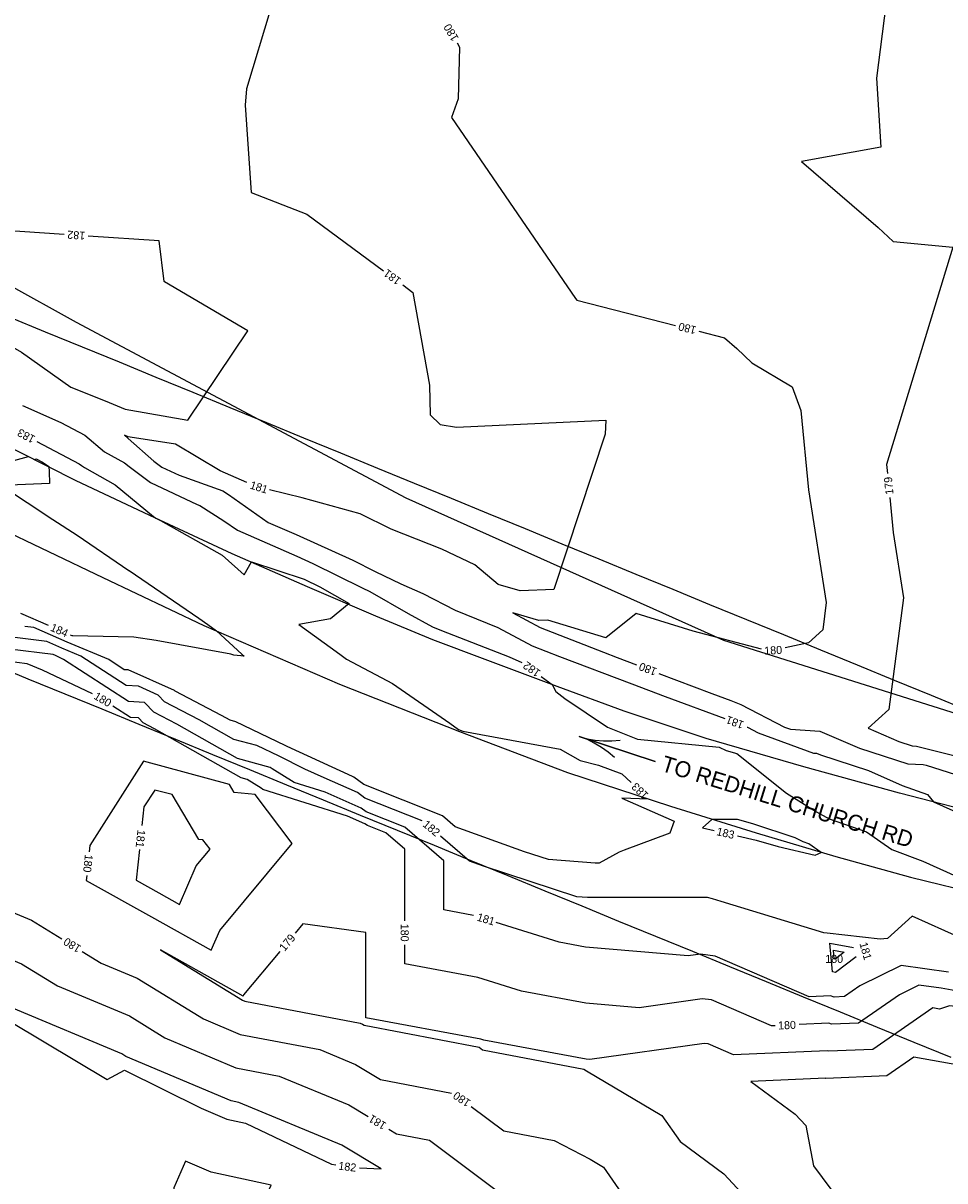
# Model space of a CAD drawing. Extents: x 2086416 to 2115205, y 575507 to 632762.
# Drawn here: x 2110689 to 2110919.3, y 581570.2 to 581859.5 of the extents above; entities that cross this region are included whole.
import ezdxf

# ---------------------------------------------------------------- set-up
doc = ezdxf.new("R2010")
doc.units = 0
for name, color, linetype in [('DTM Contours Major', 7, 'Continuous'), ('DTM Contours Major Text', 7, 'Continuous'), ('DTM Contours Minor', 7, 'Continuous'), ('DTM Contours Minor Text', 7, 'Continuous'), ('Exist Hydrographic FEMA Cross Section', 7, 'Continuous'), ('Exist Roads EOP', 7, 'Continuous'), ('Exist Roads EOP Text', 7, 'Continuous'), ('Exist Vegetation Woods Line', 7, 'Continuous')]:
    doc.layers.add(name, color=color, linetype=linetype)

msp = doc.modelspace()

# ---------------------------------------------------------------- linework, layer by layer
at = {"layer": 'DTM Contours Major'}
for points in [[(2110797.42, 581854.62), (2110798.05, 581853.55), (2110797.69, 581840.6), (2110795.99, 581835.94), (2110827.03, 581790.7), (2110827.32, 581790.29), (2110827.36, 581790.26), (2110852, 581783.99)], [(2110857.81, 581782.51), (2110864.26, 581780.86), (2110867.35, 581778.23), (2110871.08, 581774.64), (2110881.14, 581768.63), (2110883.33, 581762.7), (2110885.27, 581742.86), (2110889.69, 581714.76), (2110888.79, 581707.91), (2110885.2, 581704.69), (2110879.38, 581703.43)], [(2110706.28, 581691.93), (2110693.8, 581697.81), (2110690.01, 581699.43), (2110684.82, 581700.07), (2110681.7, 581701.62), (2110658.82, 581711.83), (2110658.38, 581712.2), (2110655.34, 581713.32), (2110650.98, 581714.55), (2110621.94, 581701.5), (2110616.68, 581704.25), (2110614.73, 581705.26)], [(2110873.53, 581703.08), (2110856.38, 581707.56), (2110842.13, 581711.99), (2110834.59, 581705.91), (2110820.11, 581710.34), (2110817.82, 581710.24), (2110811.38, 581712.14), (2110818.2, 581708.5), (2110833.97, 581702.31), (2110837.45, 581701), (2110842.24, 581699.17)], [(2110847.85, 581697.03), (2110861.11, 581691.96), (2110865.83, 581690.2), (2110868.29, 581689.26), (2110879.23, 581683.6), (2110880.71, 581683.05), (2110888.09, 581682.6), (2110898.02, 581678.3), (2110910.04, 581674.42), (2110913.9, 581674.27), (2110914.63, 581674.08), (2110929.32, 581669.43), (2110931.83, 581667.74), (2110941.39, 581664.51), (2110941.63, 581664.47)], [(2110784.33, 581635.17), (2110784.32, 581653.09), (2110779.63, 581657.15), (2110774.99, 581658.99), (2110774.4, 581659.43), (2110770.07, 581661.34), (2110748.91, 581668.01), (2110748.44, 581668.31), (2110744.94, 581670.52), (2110743.47, 581670.91), (2110721.78, 581683.2), (2110718.94, 581684.68), (2110717.79, 581685.89), (2110715.79, 581686.01), (2110711.42, 581688.85)], [(2110614.54, 581679.26), (2110619.08, 581680.34), (2110637.66, 581668.88), (2110655.14, 581658.09), (2110656.42, 581653.38), (2110664.82, 581649.96), (2110682.42, 581638.95), (2110691.1, 581635.36), (2110698.64, 581630.7)], [(2110738.13, 581632.78), (2110756.23, 581654.5), (2110746.95, 581666.78), (2110741.73, 581667.28), (2110740.52, 581669.29), (2110719.05, 581675.06), (2110705.66, 581654.02), (2110705.49, 581652.46)], [(2110704.85, 581646.49), (2110704.72, 581645.3), (2110721.08, 581636.15), (2110735.97, 581627.82), (2110738.13, 581632.78)], [(2110703.74, 581627.54), (2110708.49, 581624.6), (2110717.43, 581620.86), (2110734.08, 581610.65), (2110743.22, 581606.79), (2110763.09, 581602.99), (2110772.06, 581599.26), (2110778.24, 581595.53), (2110796.02, 581592.11)], [(2110876.9, 581608.98), (2110875.97, 581608.94), (2110861.02, 581615.41), (2110858.67, 581615.72), (2110842.9, 581613.47), (2110829.57, 581614.6), (2110813.49, 581617.62), (2110802.61, 581621.03), (2110784.33, 581624.43), (2110784.33, 581629.17)], [(2110891.68, 581625.67), (2110891.47, 581627.83), (2110894.17, 581627.32), (2110891.91, 581625.62), (2110891.68, 581625.67)], [(2110977.61, 581610.99), (2110974.93, 581611.41), (2110968.79, 581612.43), (2110963.33, 581613.78), (2110963.22, 581612.21), (2110955.69, 581613.08), (2110950.2, 581615.22), (2110942.99, 581615.11), (2110926.63, 581616.85), (2110918.38, 581618.34), (2110912.82, 581619.09), (2110907.96, 581616.69), (2110897.75, 581609.63), (2110890.96, 581609.35), (2110890.33, 581609.58), (2110882.9, 581609.25)], [(2110800.95, 581588.81), (2110809.09, 581582.72), (2110821.66, 581580.31), (2110830.66, 581575.58), (2110834.04, 581573.59), (2110844.63, 581558.22), (2110846.26, 581557.03), (2110861.48, 581540.67), (2110862.45, 581535.67), (2110855.94, 581535.48), (2110849.88, 581541.19)]]:
    msp.add_lwpolyline(points, dxfattribs=at)
at = {"layer": 'DTM Contours Minor'}
for points in [[(2110775.86, 581953.5), (2110764.32, 581958.22), (2110760.24, 581943.47), (2110768.82, 581917.19), (2110766.89, 581914.46), (2110769.13, 581910.61), (2110764.97, 581904.78), (2110752.13, 581868.98), (2110750.83, 581863.28), (2110744.81, 581843.13), (2110744.47, 581839.04), (2110745.98, 581817.21), (2110759.85, 581811.8), (2110779.05, 581797.65)], [(2110923.11, 581896.47), (2110920.2, 581894.07), (2110908.89, 581875.53), (2110906.44, 581872.43), (2110903.92, 581871.43), (2110905.1, 581868.04), (2110902.25, 581845.78), (2110903.28, 581828.56), (2110883.48, 581824.9), (2110902.68, 581808.48), (2110906.39, 581804.92), (2110921.27, 581803.56), (2110904.76, 581749.19), (2110904.98, 581746.94)], [(2110699.21, 581806.73), (2110683.26, 581807.82), (2110671.77, 581786.48), (2110683.44, 581780.2), (2110688.54, 581777.3), (2110700.9, 581768.53), (2110709.47, 581765.13), (2110714.47, 581763.07)], [(2110714.47, 581763.07), (2110730.11, 581760.27), (2110745.1, 581782.66), (2110724.29, 581794.88), (2110724.2, 581794.91), (2110722.93, 581805.1), (2110705.19, 581806.32)], [(2110783.88, 581794.09), (2110786.38, 581792.24), (2110790.55, 581769.06), (2110790.67, 581761.66), (2110793.22, 581759.21), (2110797.3, 581758.53), (2110834.58, 581760.33), (2110834.42, 581756.77), (2110821.6, 581718.02), (2110813.16, 581717.66), (2110807.7, 581719.27), (2110801.81, 581724.13), (2110793.61, 581728.02), (2110780.97, 581733.08), (2110773.17, 581736.89), (2110758.67, 581740.86), (2110750.54, 581742.89)], [(2110688.77, 581763.93), (2110698.41, 581759.72), (2110704.41, 581756.57), (2110709.32, 581752.37), (2110714.34, 581749.66), (2110715.43, 581748.68), (2110720.79, 581744.69), (2110732.5, 581739.25), (2110733.16, 581739.01), (2110739.12, 581735.16), (2110742.54, 581732.77), (2110757.35, 581726.29), (2110761.4, 581724.45), (2110773.69, 581718.38), (2110775.58, 581717.45), (2110785.2, 581711.98), (2110791.25, 581708.61), (2110793.49, 581707.73), (2110810.4, 581701.16), (2110813.56, 581699.74)], [(2110692.36, 581754.97), (2110702.99, 581749.38), (2110703.53, 581748.93), (2110704.33, 581748.49), (2110711.97, 581744.12), (2110721.57, 581736.26), (2110722.09, 581735.79), (2110723.27, 581735.2), (2110738.74, 581726.59), (2110744.19, 581721.64), (2110746.05, 581724.86), (2110759.16, 581720.54), (2110763.09, 581718.65), (2110770.46, 581714.45), (2110765.74, 581710.68), (2110757.84, 581709.2), (2110768.09, 581701.86), (2110769.74, 581700.6), (2110781.3, 581694.48), (2110795.58, 581684.55), (2110797.77, 581683.02), (2110798.85, 581682.54), (2110823.21, 581678.05), (2110828.17, 581675.21), (2110832.75, 581674.08), (2110838.55, 581671.95), (2110840.9, 581669.72)], [(2110744.84, 581744.68), (2110738.18, 581747.62), (2110727.08, 581754.3), (2110715.7, 581756.04), (2110715.25, 581756.12), (2110714.3, 581756.51), (2110715.11, 581755.81), (2110715.25, 581755.74), (2110721.64, 581750.04), (2110723.61, 581748.57), (2110727.93, 581746.56), (2110738.89, 581742.6), (2110740.3, 581741.69), (2110750.22, 581734.74), (2110757.2, 581731.69), (2110771.37, 581725.27), (2110776.96, 581722.51), (2110783.38, 581719.36), (2110788.87, 581717), (2110796.93, 581712.8), (2110807.57, 581708.49), (2110816.16, 581703.9), (2110822.98, 581701.22), (2110841.1, 581694.44), (2110849.4, 581691.27), (2110864.3, 581685.71)], [(2110678.29, 581747.94), (2110690.29, 581751.21), (2110691.99, 581750.37), (2110692.19, 581750.63), (2110693.8, 581749.81), (2110695.06, 581748.94), (2110695.41, 581748.69), (2110695.46, 581747.45), (2110695.55, 581744.5), (2110683.59, 581743.96), (2110696.4, 581735.45), (2110702.5, 581731.53), (2110715.41, 581722.75), (2110715.47, 581722.71), (2110732.91, 581710.78), (2110735.1, 581709.24), (2110737.26, 581707.64), (2110743.62, 581701.84), (2110744.21, 581701.3), (2110741.62, 581701.53), (2110740.86, 581701.85), (2110722.22, 581705.24), (2110716.61, 581706.04), (2110712.68, 581706.13), (2110701.37, 581706.37), (2110701.31, 581706.38), (2110701.24, 581706.39), (2110700.82, 581706.57)], [(2110905.56, 581740.96), (2110906.42, 581732.25), (2110908.99, 581715.89), (2110905.35, 581687.97), (2110900.14, 581683.3), (2110907.85, 581679.96), (2110911.1, 581678.91), (2110912.22, 581678.87), (2110926.91, 581675.14), (2110932.8, 581673.28), (2110935.94, 581671.16), (2110944.78, 581668.87), (2110956.33, 581666.68), (2110959.91, 581665.57), (2110973.62, 581663.25), (2110979.88, 581661.39), (2110993.91, 581658.93), (2111006.74, 581655.37), (2111011.49, 581654.3), (2111022.59, 581651.38), (2111027.31, 581652.26), (2111030.98, 581649.79), (2111034.24, 581649.51)], [(2110695.32, 581708.96), (2110688.38, 581711.98)], [(2110845.22, 581665.6), (2110838.61, 581665.84), (2110851.69, 581660.12), (2110850.58, 581657.12), (2110839.13, 581652.88), (2110837.96, 581652.36), (2110832.9, 581649.56), (2110831.96, 581649.56), (2110820.28, 581650.5), (2110814.3, 581652.46), (2110796.93, 581658.68), (2110793.73, 581661.45), (2110774.09, 581669.24), (2110771.57, 581671.12), (2110771.27, 581671.26), (2110754.92, 581678.76), (2110754.43, 581679.01), (2110742.11, 581684.91), (2110740.67, 581685.29), (2110738.52, 581686.51), (2110726.99, 581692.55), (2110726.82, 581692.73), (2110715.25, 581697.88), (2110714.22, 581697.94), (2110710.36, 581700.45), (2110700, 581704.85), (2110691.63, 581708.49), (2110689.36, 581708.77)], [(2110788.71, 581660.14), (2110774.39, 581665.82), (2110772.51, 581667.23), (2110764.23, 581670.88), (2110759.35, 581673.12), (2110752.95, 581676.29), (2110747.39, 581678.96), (2110741.61, 581680.5), (2110732.94, 581685.41), (2110724.31, 581689.93), (2110722.74, 581691.58), (2110717.79, 581693.79), (2110714.74, 581693.96), (2110703.39, 581701.35), (2110698.68, 581703.34), (2110694.89, 581704.99), (2110686.26, 581706.07)], [(2110801.48, 581636.52), (2110794.09, 581637.9), (2110794.08, 581650.15), (2110784.33, 581658.58), (2110774.69, 581662.4), (2110773.46, 581663.33), (2110764.45, 581667.3), (2110756.74, 581669.73), (2110751.23, 581673.2), (2110750.71, 581673.53), (2110742.54, 581675.71), (2110727.36, 581684.3), (2110721.62, 581687.31), (2110719.3, 581689.75), (2110715.26, 581689.99), (2110699.06, 581700.52), (2110697.04, 581701.47), (2110696.5, 581701.71), (2110685.54, 581703.07)], [(2110818.44, 581696.27), (2110821.2, 581694.21), (2110822.09, 581692.5), (2110824.38, 581690.77), (2110834.99, 581683.55), (2110842.52, 581680.61), (2110862.89, 581678.56), (2110864.67, 581677.73), (2110867.29, 581676.98), (2110879.75, 581667.09), (2110887.27, 581662.38), (2110890.41, 581660.71), (2110899.69, 581657.39), (2110906.1, 581653), (2110913.79, 581650.08), (2110926.59, 581644.34)], [(2110869.92, 581683.61), (2110870.01, 581683.58), (2110872.69, 581682.19), (2110886.48, 581677.11), (2110887.21, 581677.07), (2110888.2, 581676.64), (2110900.23, 581672.75), (2110908.61, 581668.98), (2110914.95, 581666.77), (2110916.46, 581664.89), (2110928.52, 581659.48), (2110932.08, 581657.5), (2110940.41, 581652.05), (2110959.88, 581648.42), (2110971.42, 581648.11), (2110976.77, 581647.17), (2110988.63, 581643.91), (2111000.53, 581640.56), (2111020.53, 581635.11), (2111024.4, 581634.03), (2111046.82, 581629.45), (2111048.5, 581629.07), (2111048.77, 581629), (2111059.73, 581627.25)], [(2110604.39, 581671.28), (2110610.61, 581661.99), (2110624.31, 581665.25), (2110632.56, 581660.16), (2110640.32, 581655.37), (2110643.15, 581644.99), (2110661.66, 581637.44), (2110670.37, 581631.99), (2110688.6, 581624.45), (2110697.54, 581618.92), (2110715.51, 581611.4), (2110724.37, 581605.97), (2110742.09, 581598.48), (2110752.98, 581596.4), (2110770.33, 581589.17), (2110775.18, 581586.24)], [(2110732.22, 581648.91), (2110735.7, 581653.09), (2110733.91, 581655.45), (2110732.91, 581655.54), (2110726.18, 581666.71), (2110721.86, 581667.87), (2110719.16, 581663.63), (2110718.66, 581658.97)], [(2110885.29, 581654.39), (2110883.87, 581654.9), (2110881.88, 581655.95), (2110871.29, 581659.4), (2110867.53, 581660.53), (2110861.07, 581660.53), (2110858.75, 581658.42), (2110861.64, 581657.76)], [(2110923.38, 581630.81), (2110911.16, 581636.31), (2110911.1, 581636.32), (2110904.94, 581630.73), (2110903.18, 581630.56), (2110889.88, 581632.09), (2110889.08, 581632.18), (2110863.41, 581639.97), (2110861.22, 581640.65), (2110861.21, 581640.65), (2110860.03, 581641), (2110859.55, 581641.04), (2110830.03, 581640.99), (2110827.32, 581641.21), (2110803.98, 581648.87), (2110800.48, 581650.12), (2110793.31, 581656.32)], [(2110867.49, 581656.41), (2110872.18, 581655.33), (2110877.68, 581653.75), (2110886.89, 581651.63), (2110888.4, 581652.26), (2110885.29, 581654.39)], [(2110718.03, 581653), (2110717.21, 581645.33), (2110722.87, 581642.16), (2110728.03, 581639.28), (2110732.22, 581648.91)], [(2110929.04, 581613.04), (2110920.49, 581613.95), (2110917.95, 581613.11), (2110916.27, 581613.41), (2110901.27, 581603.04), (2110890.27, 581602.57), (2110889.9, 581602.71), (2110866.52, 581601.67), (2110860.13, 581604.43), (2110859.13, 581604.56), (2110830.62, 581600.5), (2110829.64, 581600.58), (2110804.08, 581605.37), (2110803.32, 581605.61), (2110774.57, 581610.97), (2110774.57, 581632.28), (2110758.83, 581634.4), (2110756.92, 581632.1)], [(2110920.18, 581622.39), (2110908.4, 581623.98), (2110898.09, 581618.9), (2110894.23, 581616.23), (2110891.66, 581616.12), (2110890.77, 581616.45), (2110885.42, 581616.21), (2110861.9, 581626.39), (2110858.22, 581626.88), (2110855.17, 581626.45), (2110829.5, 581628.62), (2110822.89, 581629.86), (2110807.22, 581634.78)], [(2110753.08, 581627.49), (2110744.05, 581616.65), (2110743.92, 581616.36), (2110723.28, 581627.9), (2110743.8, 581615.32), (2110744.35, 581615.09), (2110773.2, 581609.58), (2110773.78, 581609.34), (2110774.18, 581609.1), (2110802.91, 581603.58), (2110803.77, 581602.94), (2110829.06, 581598.07), (2110829.72, 581597.73), (2110848.6, 581586.56), (2110853.13, 581580), (2110864.1, 581571.94), (2110868.48, 581567.23)], [(2110891.27, 581622.44), (2110890.57, 581629.59), (2110896.48, 581628.48)], [(2110897.15, 581626.15), (2110892.02, 581622.27), (2110891.27, 581622.44)], [(2110742.87, 581589.81), (2110740.96, 581590.18), (2110714.65, 581601.3), (2110713.6, 581601.94), (2110686.58, 581613.24), (2110686.1, 581613.54), (2110665.95, 581621.88), (2110677.38, 581609.19), (2110686.18, 581609.76), (2110710, 581595.5), (2110714.28, 581597.88), (2110733.49, 581588.34), (2110739.88, 581585.59), (2110744.53, 581584.59), (2110766.06, 581574.38), (2110767.08, 581574.21)], [(2110925.52, 581598.64), (2110911.57, 581601.13), (2110904.79, 581596.44), (2110889.57, 581595.8), (2110889.46, 581595.84), (2110870.84, 581595.01), (2110881.93, 581586.86), (2110884.54, 581584.07), (2110886.49, 581573.95), (2110895.38, 581561.98), (2110911.97, 581539.46)], [(2110773.03, 581573.48), (2110778.41, 581573.17), (2110768.6, 581579.09), (2110742.87, 581589.81)], [(2110780.32, 581583.14), (2110782.3, 581581.95), (2110790.5, 581580.38), (2110813.88, 581562.9), (2110805.64, 581559.71), (2110784.07, 581564.67), (2110780.03, 581564.9), (2110766.38, 581567.1), (2110767.94, 581544.14), (2110743.89, 581553.54), (2110750.95, 581569.13), (2110735.94, 581572.34), (2110729.52, 581575.11), (2110726.6, 581568.42), (2110727.73, 581552.75)]]:
    msp.add_lwpolyline(points, dxfattribs=at)
at = {"layer": 'Exist Hydrographic FEMA Cross Section'}
for points in [[(2110925.19, 581687.7), (2110915.97, 581691.48), (2110906.74, 581695.27), (2110897.52, 581699.06), (2110888.29, 581702.84), (2110879.07, 581706.62), (2110869.84, 581710.41), (2110860.61, 581714.19), (2110851.39, 581717.98), (2110842.16, 581721.76), (2110832.94, 581725.55), (2110823.71, 581729.33), (2110814.49, 581733.12), (2110805.27, 581736.9), (2110796.04, 581740.69), (2110786.81, 581744.47), (2110777.59, 581748.26), (2110768.36, 581752.04), (2110759.14, 581755.83), (2110749.91, 581759.61), (2110740.69, 581763.39), (2110731.46, 581767.18), (2110722.23, 581770.97), (2110713.01, 581774.75), (2110703.79, 581778.53), (2110694.56, 581782.32), (2110685.33, 581786.1)], [(2110920.89, 581600.99), (2110911.67, 581604.77), (2110902.44, 581608.56), (2110893.22, 581612.34), (2110883.99, 581616.13), (2110874.77, 581619.91), (2110865.54, 581623.7), (2110856.32, 581627.48), (2110847.09, 581631.27), (2110837.86, 581635.05), (2110828.64, 581638.84), (2110819.42, 581642.62), (2110810.19, 581646.4), (2110800.96, 581650.19), (2110791.74, 581653.98), (2110782.52, 581657.76), (2110773.29, 581661.54), (2110764.06, 581665.33), (2110754.84, 581669.11), (2110745.61, 581672.9), (2110736.39, 581676.69), (2110727.16, 581680.47), (2110717.94, 581684.25), (2110708.71, 581688.04), (2110699.48, 581691.82), (2110690.26, 581695.61), (2110681.04, 581699.39)]]:
    msp.add_lwpolyline(points, dxfattribs=at)
at = {"layer": 'Exist Roads EOP'}
for points in [[(2110859.62, 581680.71), (2110839.18, 581687.57), (2110822.39, 581693.78), (2110804.41, 581700.49), (2110791.36, 581705.43), (2110777.14, 581711.28), (2110760, 581718.68), (2110741.24, 581726.89), (2110721.85, 581735.85), (2110702.22, 581745.1), (2110680.73, 581755.98), (2110662.27, 581765.85), (2110648.84, 581772.92), (2110632.22, 581782.31), (2110614.63, 581792.7), (2110596.64, 581803.91), (2110578.53, 581815.64), (2110567.83, 581822.57), (2110553.15, 581832.42), (2110531.54, 581847.48), (2110510.05, 581863.33), (2110489.25, 581879.31), (2110463.15, 581900.73), (2110445.32, 581916.19)], [(2110454.4, 581883.19), (2110469.83, 581870.54), (2110488.57, 581855.49), (2110506.88, 581841.42), (2110523.82, 581828.96), (2110539, 581818.5), (2110552.64, 581809.38), (2110568.55, 581798.72), (2110587.98, 581786.4), (2110607.77, 581774.2), (2110633.24, 581759.62), (2110661.71, 581744.29), (2110681.63, 581733.96), (2110708.85, 581721.01), (2110734.15, 581708.98), (2110768.01, 581694.36), (2110797.99, 581682.47), (2110825.02, 581672.22), (2110850.72, 581663.8), (2110872.12, 581657.17), (2110892.09, 581651.25), (2110910.76, 581646.06), (2110929.15, 581641.61)], [(2110977.48, 581650.48), (2110956.38, 581655.31), (2110931.86, 581660.94), (2110907.94, 581667.06), (2110884.07, 581673.67), (2110859.62, 581680.71)]]:
    msp.add_lwpolyline(points, dxfattribs=at)
at = {"layer": 'Exist Roads EOP Text'}
msp.add_line((2110837.43, 581678.14), (2110837.43, 581678.14), dxfattribs=at)
msp.add_lwpolyline([(2110836.72, 581675.97), (2110835.17, 581677.31), (2110833.49, 581678.53), (2110831.71, 581679.61), (2110829.86, 581680.55), (2110827.93, 581681.26), (2110846.94, 581675.03), (2110827.93, 581681.26), (2110829.9, 581680.69), (2110831.95, 581680.35), (2110834.03, 581680.17), (2110836.11, 581680.16), (2110838.15, 581680.32)], dxfattribs=at)
at = {"layer": 'Exist Vegetation Woods Line'}
msp.add_lwpolyline([(2111059.79, 581657.65), (2110968.73, 581672.25), (2110864.06, 581705.25), (2110784.73, 581740.8), (2110702.3, 581784.67), (2110632.54, 581823.34), (2110568.48, 581865.95), (2110498.27, 581913.79), (2110441.66, 581966.78), (2110387.94, 582016.39), (2110334.43, 582063.69), (2110284.48, 582120.87)], dxfattribs=at)

# ---------------------------------------------------------------- texts
at = {"layer": 'DTM Contours Major Text'}
for rotation, p in [(120.6948, (2110797.91, 581855.75)), (165.7175, (2110857.36, 581783.65)), (3.366, (2110874.24, 581701.66)), (159.0867, (2110847.53, 581698.22)), (329.0924, (2110706.44, 581690.8)), (263.899, (2110704.42, 581651.84)), (270.0188, (2110783.33, 581634.45)), (148.2468, (2110703.65, 581628.77)), (2.5491, (2110877.67, 581608.01)), (146.1671, (2110801, 581590.17))]:
    msp.add_text('180', height=2, rotation=rotation, dxfattribs=at).set_placement(p)
msp.add_text('180', height=2, dxfattribs=at).set_placement((2110889.41, 581624.67))
at = {"layer": 'DTM Contours Minor Text'}
for s, rotation, p in [('182', 176.0842, (2110704.54, 581807.36)), ('181', 143.6087, (2110783.61, 581795.52)), ('183', 152.3918, (2110692.18, 581756.2)), ('179', 95.5873, (2110906.49, 581741.78)), ('181', 342.5962, (2110745.48, 581743.25)), ('184', 336.5277, (2110695.58, 581707.76)), ('182', 144.5653, (2110818.47, 581697.56)), ('181', 159.5025, (2110869.28, 581684.92)), ('183', 136.412, (2110845.42, 581666.81)), ('182', 320.256, (2110788.65, 581658.97)), ('181', 263.899, (2110717.56, 581658.02)), ('183', 347.0316, (2110862.12, 581656.62)), ('181', 343.087, (2110802.21, 581635.28)), ('179', 50.1912, (2110754.31, 581627.41)), ('181', 285.976, (2110897.94, 581629.51)), ('181', 148.8935, (2110779.93, 581584.55)), ('182', 353.0143, (2110767.66, 581573.02))]:
    msp.add_text(s, height=2, rotation=rotation, dxfattribs=at).set_placement(p)
at = {"layer": 'Exist Roads EOP Text'}
msp.add_text('TO REDHILL CHURCH RD', height=4, rotation=342.7594, dxfattribs=at).set_placement((2110848.16, 581672.74))

doc.saveas('drawing.dxf')
